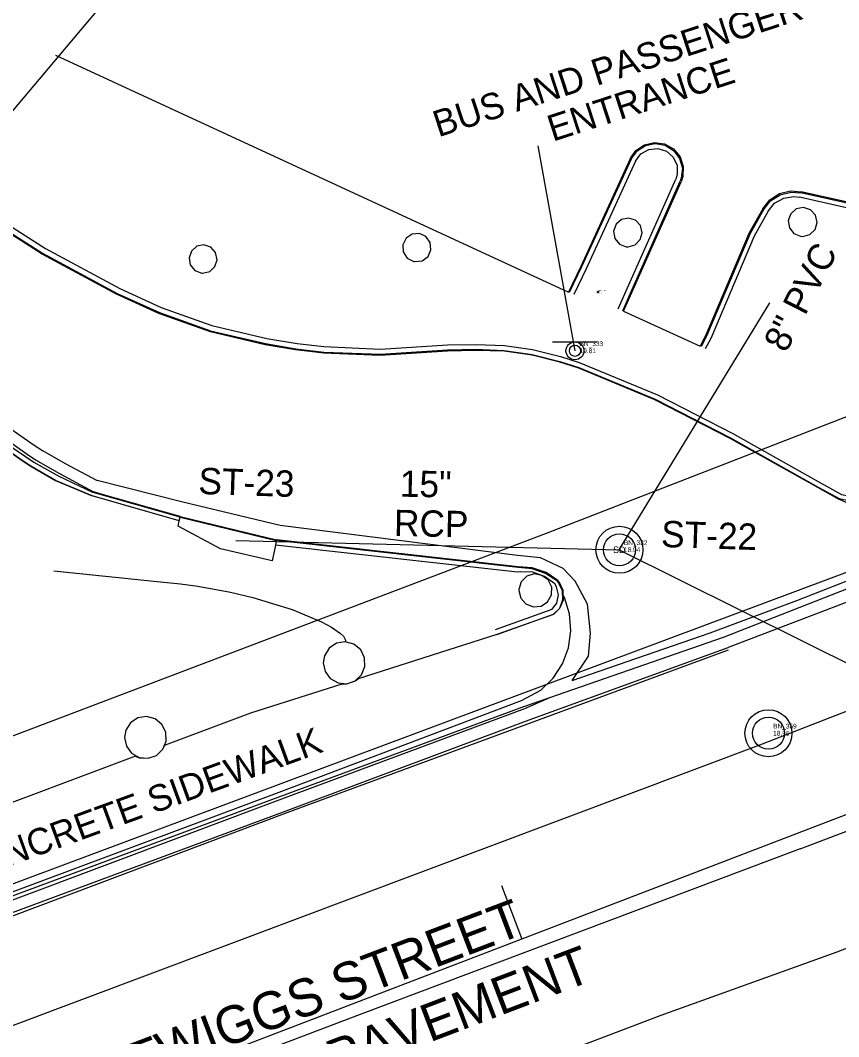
# Model space of a CAD drawing. Extents: x 509744 to 512285, y 1314862 to 1316822.
# Drawn here: x 510729.8 to 510816.7, y 1315517.7 to 1315625.7 of the extents above; entities that cross this region are included whole.
import ezdxf

# ---------------------------------------------------------------- set-up
doc = ezdxf.new("R2010")
doc.units = 0
for name, color, linetype in [('BaselineSurvey', 7, 'Continuous'), ('CGBack_ep', 7, 'Continuous'), ('CGep_ep', 7, 'Continuous'), ('CGFace_ep', 7, 'Continuous'), ('Driveway_ep', 7, 'Continuous'), ('ElecAer_ep', 7, 'Continuous'), ('GroundShot_ep', 7, 'Continuous'), ('InletCurb_ep', 7, 'Continuous'), ('LaneLine_ep', 7, 'Continuous'), ('LARWLine_ep', 7, 'Continuous'), ('ManholeSW_ep', 7, 'Continuous'), ('ManholeUnknown_ep', 7, 'Continuous'), ('NonPlottingEle_dp', 7, 'Continuous'), ('PavtAsphalt_ep', 7, 'Continuous'), ('PavtAsphaltCrown_ep', 7, 'Continuous'), ('PilingColumn_ep', 7, 'Continuous'), ('PipeCulvert_ep', 7, 'Continuous'), ('PMRK_ep', 7, 'Continuous'), ('SidewalkBack_ep', 7, 'Continuous'), ('SignSingle_ep', 7, 'Continuous'), ('TextElevLabel', 7, 'Continuous'), ('TextPtLabel', 7, 'Continuous'), ('TextTopoLabel_ep', 7, 'Continuous')]:
    doc.layers.add(name, color=color, linetype=linetype)

msp = doc.modelspace()

# ---------------------------------------------------------------- linework, layer by layer
at = {"layer": 'BaselineSurvey'}
for p, q in [((509756.06, 1315134.11), (510956.77, 1315594.74)), ((510783.08, 1315528.11), (510780.93, 1315533.71))]:
    msp.add_line(p, q, dxfattribs=at)
at = {"layer": 'CGBack_ep'}
for p, q in [((510746.65, 1315572.52), (510737.41, 1315575.2)), ((510782.61, 1315567.08), (510756.88, 1315569.96)), ((510786.26, 1315563.09), (510780.23, 1315560.95))]:
    msp.add_line(p, q, dxfattribs=at)
for points in [[(510737.41, 1315575.2), (510733.49, 1315576.82), (510730.86, 1315578.34), (510729.97, 1315578.94), (510727.51, 1315580.64), (510725.08, 1315582.41), (510722.77, 1315584.35), (510721.08, 1315585.67), (510709.18, 1315595.32), (510686.17, 1315614.58), (510666.79, 1315630.63)], [(510666.79, 1315630.63), (510686.17, 1315614.58), (510709.18, 1315595.32), (510721.08, 1315585.67), (510722.77, 1315584.35), (510725.08, 1315582.41), (510727.51, 1315580.64), (510729.97, 1315578.94), (510730.86, 1315578.34), (510733.49, 1315576.82), (510737.41, 1315575.2)], [(510795.16, 1315610.77), (510795.73, 1315611.55), (510796.56, 1315612.02), (510797.52, 1315612.13), (510798.44, 1315611.83), (510799.16, 1315611.2), (510799.57, 1315610.32), (510799.59, 1315609.36), (510799.43, 1315608.85)], [(510795.16, 1315610.77), (510789.9, 1315599.32), (510788.59, 1315596.59)], [(510793.32, 1315595.08), (510794.03, 1315596.65), (510799.43, 1315608.85)], [(510809.24, 1315605.45), (510809.94, 1315606.3), (510810.9, 1315606.84), (510811.98, 1315607.01), (510812.57, 1315606.94)], [(510817.57, 1315605.8), (510812.57, 1315606.94)], [(510725.8, 1315605.69), (510732.42, 1315601.49), (510740.33, 1315597.22), (510744.74, 1315595.23), (510750.12, 1315593.3), (510755.96, 1315591.92), (510759.18, 1315591.39), (510762.03, 1315591.05), (510768.03, 1315590.78), (510775.17, 1315591.25), (510778.23, 1315591.29), (510781.23, 1315591.16), (510784.21, 1315590.76), (510787.16, 1315590.01), (510789.17, 1315589.37), (510797.48, 1315585.93), (510805.5, 1315581.83), (510814.81, 1315576.58), (510817.04, 1315575.34), (510819.79, 1315574.76), (510822.54, 1315575.56), (510828.16, 1315577.64), (510830.98, 1315578.69), (510831.57, 1315578.9)], [(510809.24, 1315605.45), (510807.77, 1315602.81), (510803.14, 1315591.91), (510802.57, 1315590.81)], [(510786.56, 1315565.83), (510785.49, 1315566.62), (510784.24, 1315567.06), (510782.92, 1315567.12), (510782.61, 1315567.08)], [(510786.26, 1315563.09), (510786.8, 1315563.79), (510786.97, 1315564.66), (510786.75, 1315565.52), (510786.56, 1315565.83)], [(510785.1, 1315554.51), (510786.4, 1315555.79), (510787.39, 1315557.32), (510788.03, 1315559.02), (510788.28, 1315560.83), (510788.13, 1315562.64), (510787.59, 1315564.38), (510787.53, 1315564.51)], [(510717.8, 1315528.92), (510757.28, 1315543.68), (510783.02, 1315553.43), (510785.1, 1315554.51)]]:
    msp.add_lwpolyline(points, dxfattribs=at)
at = {"layer": 'CGep_ep'}
for p, q in [((510782.68, 1315567.64), (510756.99, 1315570.52)), ((510786.42, 1315562.57), (510780.41, 1315560.46)), ((510786.06, 1315553.74), (510804.49, 1315560.17))]:
    msp.add_line(p, q, dxfattribs=at)
for points in [[(510667.94, 1315630.71), (510686.68, 1315615.13), (510709.65, 1315595.9), (510721.53, 1315586.23), (510723.21, 1315584.89), (510725.56, 1315583.06), (510728.03, 1315581.34), (510730.49, 1315579.63), (510731.38, 1315579.03), (510733.92, 1315577.57), (510737.54, 1315575.61)], [(510746.75, 1315573), (510738.35, 1315575.38), (510737.54, 1315575.61)], [(510746.75, 1315573), (510754.93, 1315571), (510756.99, 1315570.52)], [(510804.49, 1315560.17), (510821.42, 1315566.79), (510835.46, 1315572.07)], [(510786.91, 1315566.17), (510785.64, 1315567.02), (510784.18, 1315567.52), (510782.68, 1315567.64)], [(510786.42, 1315562.57), (510787.12, 1315563.25), (510787.49, 1315564.14), (510787.47, 1315565.11), (510787.06, 1315565.98), (510786.91, 1315566.17)], [(510719.67, 1315528.77), (510757.54, 1315542.97), (510783.38, 1315552.57), (510786.06, 1315553.74)]]:
    msp.add_lwpolyline(points, dxfattribs=at)
at = {"layer": 'CGFace_ep'}
for points in [[(510667.61, 1315630.66), (510686.5, 1315614.93), (510709.48, 1315595.7), (510721.36, 1315586.02), (510723.05, 1315584.7), (510725.37, 1315582.8), (510727.83, 1315581.08), (510730.3, 1315579.37), (510731.19, 1315578.78), (510733.78, 1315577.31), (510737.52, 1315575.56)], [(510794.69, 1315610.99), (510795.31, 1315611.86), (510796.2, 1315612.44), (510797.24, 1315612.65), (510798.29, 1315612.47), (510799.2, 1315611.91), (510799.84, 1315611.06), (510800.13, 1315610.04), (510800.02, 1315608.98), (510799.9, 1315608.64)], [(510794.69, 1315610.99), (510789.42, 1315599.55), (510788.1, 1315596.82)], [(510793.79, 1315594.86), (510794.46, 1315596.41), (510799.9, 1315608.64)], [(510808.74, 1315605.61), (510809.49, 1315606.55), (510810.51, 1315607.19), (510811.68, 1315607.47), (510812.69, 1315607.39)], [(510817.66, 1315606.31), (510812.69, 1315607.39)], [(510808.74, 1315605.61), (510807.33, 1315603.08), (510802.69, 1315592.15), (510802.12, 1315591.05)], [(510725.41, 1315605.24), (510732.13, 1315600.99), (510740.05, 1315596.72), (510744.54, 1315594.69), (510749.99, 1315592.74), (510755.83, 1315591.37), (510759.04, 1315590.83), (510762.03, 1315590.47), (510768.03, 1315590.24), (510775.17, 1315590.71), (510778.19, 1315590.78), (510781.19, 1315590.64), (510784.16, 1315590.23), (510787.11, 1315589.48), (510789.12, 1315588.84), (510797.24, 1315585.46), (510805.25, 1315581.36), (510814.55, 1315576.12), (510816.8, 1315574.92), (510819.69, 1315574.29), (510822.69, 1315575.14), (510828.31, 1315577.22), (510831.13, 1315578.27), (510831.72, 1315578.48)], [(510746.74, 1315572.92), (510737.52, 1315575.56)], [(510717.96, 1315528.51), (510729.22, 1315532.75), (510757.44, 1315543.24), (510783.29, 1315552.78), (510786.06, 1315553.74)]]:
    msp.add_lwpolyline(points, dxfattribs=at)
at = {"layer": 'Driveway_ep'}
for p, q in [((510733.5, 1315622.05), (510788.04, 1315596.86)), ((510793.89, 1315594.81), (510800, 1315608.59)), ((510793.89, 1315594.81), (510802.01, 1315591.1))]:
    msp.add_line(p, q, dxfattribs=at)
for points in [[(510668.18, 1315632.26), (510687.57, 1315616.1), (510710.48, 1315596.92), (510722.36, 1315587.25), (510724.06, 1315585.94), (510726.31, 1315584.05), (510728.75, 1315582.3), (510731.22, 1315580.59), (510732.11, 1315580), (510734.53, 1315578.61), (510737.93, 1315576.83)], [(510794.58, 1315611.03), (510795.2, 1315611.92), (510796.1, 1315612.52), (510797.16, 1315612.77), (510798.24, 1315612.61), (510799.18, 1315612.08), (510799.88, 1315611.24), (510800.23, 1315610.22), (510800.18, 1315609.13), (510800, 1315608.59)], [(510794.58, 1315611.03), (510789.35, 1315599.58), (510788.04, 1315596.86)], [(510862.42, 1315590.32), (510862.8, 1315591.06), (510863.34, 1315592.39), (510863.64, 1315594.19), (510863.51, 1315595.69), (510862.64, 1315598.57), (510862.4, 1315599.05), (510860.68, 1315601.51), (510858.97, 1315603.41), (510856.66, 1315605.36), (510854.02, 1315606.78), (510851.89, 1315607.7), (510848.99, 1315608.42), (510846.01, 1315608.77), (510845.34, 1315608.77), (510839.35, 1315608.16), (510836.4, 1315607.62), (510832.77, 1315606.91), (510827.02, 1315606.06), (510824.02, 1315605.91), (510821.02, 1315606.02), (510820.64, 1315606.01), (510817.68, 1315606.41), (510812.74, 1315607.53)], [(510808.67, 1315605.71), (510809.42, 1315606.66), (510810.44, 1315607.32), (510811.62, 1315607.61), (510812.74, 1315607.53)], [(510808.67, 1315605.71), (510807.23, 1315603.14), (510802.58, 1315592.2), (510802.01, 1315591.1)], [(510832.44, 1315571.96), (510829.41, 1315571.84), (510825.35, 1315571.97), (510821.57, 1315572.75), (510816.74, 1315574.82), (510814.52, 1315576.06), (510805.22, 1315581.3), (510797.21, 1315585.4), (510789.12, 1315588.78), (510787.11, 1315589.41), (510784.16, 1315590.16), (510781.18, 1315590.57), (510778.18, 1315590.64), (510775.16, 1315590.57), (510768.02, 1315590.1), (510762.03, 1315590.35), (510759.02, 1315590.71), (510755.8, 1315591.25), (510749.96, 1315592.63), (510744.5, 1315594.58), (510739.99, 1315596.62), (510732.07, 1315600.88), (510725.35, 1315605.16)], [(510788.43, 1315555.54), (510790.17, 1315558.13), (510790.37, 1315560.6), (510790.06, 1315563.68), (510788.75, 1315566.1), (510787.45, 1315567.47), (510785.04, 1315568.58), (510782.62, 1315568.85), (510757.37, 1315572.02), (510747.05, 1315574.52), (510737.93, 1315576.83)], [(510788.43, 1315555.54), (510803.09, 1315560.61), (510812.3, 1315564.06), (510832.44, 1315571.96)]]:
    msp.add_lwpolyline(points, dxfattribs=at)
at = {"layer": 'ElecAer_ep'}
msp.add_lwpolyline([(510673.59, 1315425.92), (510652.87, 1315530.2), (510676.08, 1315553.36), (510865.37, 1315778.14)], dxfattribs=at)
at = {"layer": 'GroundShot_ep'}
for p, q in [((510791.17, 1315596.73), (510791.17, 1315596.98)), ((510791.29, 1315596.86), (510791.04, 1315596.86))]:
    msp.add_line(p, q, dxfattribs=at)
at = {"layer": 'InletCurb_ep'}
msp.add_lwpolyline([(510756.97, 1315570.44), (510756.88, 1315569.96), (510756.53, 1315568.27), (510751.04, 1315569.55), (510746.54, 1315571.97), (510746.65, 1315572.52), (510746.74, 1315572.92)], close=True, dxfattribs=at)
at = {"layer": 'LaneLine_ep'}
for points in [[(511061.54, 1315628.93), (511044.44, 1315627.39), (511035.76, 1315626.13), (511004.66, 1315620.37), (510995.94, 1315617.75), (510966.1, 1315607.9), (510957.71, 1315604.65), (510928.62, 1315594.05), (510919.98, 1315590.9), (510890.84, 1315579.91), (510852.48, 1315565.44), (510817.09, 1315552.08), (510808.62, 1315548.79)], [(510816.6, 1315526.69), (510837.31, 1315534.81), (510873.94, 1315548.81), (510895.29, 1315556.58), (510940.23, 1315574.31), (510982.42, 1315590.03), (510986.67, 1315591.45), (511017.56, 1315600.61), (511033.42, 1315603.87), (511064.33, 1315607.05)], [(510640.96, 1315460.4), (510676.28, 1315473.76), (510723.03, 1315491.51), (510797.88, 1315519.97), (510816.6, 1315526.69)]]:
    msp.add_lwpolyline(points, dxfattribs=at)
at = {"layer": 'LARWLine_ep'}
for p, q in [((510994.57, 1315652.44), (510785.64, 1315571.2)), ((510785.64, 1315571.2), (510586.6, 1315495.53))]:
    msp.add_line(p, q, dxfattribs=at)
at = {"layer": 'ManholeSW_ep'}
for radius in [2.5, 1.7]:
    msp.add_circle((510793.44, 1315569.45), radius, dxfattribs=at)
at = {"layer": 'ManholeUnknown_ep'}
for radius in [2.5, 1.7]:
    msp.add_circle((510809.28, 1315549.95), radius, dxfattribs=at)
at = {"layer": 'PavtAsphalt_ep'}
for points in [[(510836.08, 1315570.49), (510821.91, 1315565.53), (510805, 1315559.08)], [(510758, 1315541.71), (510783.83, 1315551.37), (510805, 1315559.08), (510805, 1315559.08)], [(510589.41, 1315479.17), (510591.74, 1315480.02), (510664.28, 1315506.82), (510711.13, 1315524.28), (510758, 1315541.71)]]:
    msp.add_lwpolyline(points, dxfattribs=at)
at = {"layer": 'PavtAsphaltCrown_ep'}
for points in [[(510812.66, 1315537.66), (510840.71, 1315548.34), (510875.46, 1315561.64), (510912.48, 1315575.94), (510943.39, 1315587.16), (510967.06, 1315595.76)], [(510812.66, 1315537.66), (510765.87, 1315520.04), (510719.12, 1315502.28), (510621.06, 1315465.12)]]:
    msp.add_lwpolyline(points, dxfattribs=at)
at = {"layer": 'PilingColumn_ep'}
for points in [[(510812.93, 1315602.77), (510813.68, 1315602.98), (510814.23, 1315603.52), (510814.45, 1315604.27), (510814.27, 1315605.03), (510813.74, 1315605.6), (510813, 1315605.85), (510812.24, 1315605.7), (510811.65, 1315605.19), (510811.38, 1315604.47), (510811.5, 1315603.7), (510811.98, 1315603.08), (510812.7, 1315602.79)], [(510794.37, 1315601.67), (510795.12, 1315601.88), (510795.66, 1315602.43), (510795.87, 1315603.17), (510795.69, 1315603.93), (510795.16, 1315604.49), (510794.42, 1315604.73), (510793.66, 1315604.57), (510793.08, 1315604.06), (510792.82, 1315603.32), (510792.95, 1315602.56), (510793.44, 1315601.96), (510794.17, 1315601.68)], [(510771.71, 1315600.09), (510772.48, 1315600.19), (510773.1, 1315600.65), (510773.4, 1315601.36), (510773.32, 1315602.13), (510772.87, 1315602.75), (510772.18, 1315603.08), (510771.41, 1315603.02), (510770.77, 1315602.58), (510770.43, 1315601.89), (510770.47, 1315601.12), (510770.89, 1315600.47), (510771.57, 1315600.12)], [(510749.14, 1315598.87), (510749.89, 1315599.04), (510750.45, 1315599.56), (510750.68, 1315600.29), (510750.52, 1315601.05), (510750.01, 1315601.62), (510749.28, 1315601.87), (510748.53, 1315601.72), (510747.95, 1315601.22), (510747.7, 1315600.5), (510747.83, 1315599.74), (510748.32, 1315599.15), (510749.04, 1315598.88)], [(510782.76, 1315565.13), (510782.96, 1315564.32), (510783.5, 1315563.69), (510784.28, 1315563.39), (510785.11, 1315563.47), (510785.8, 1315563.93), (510786.21, 1315564.65), (510786.24, 1315565.49), (510785.88, 1315566.24), (510785.19, 1315566.71), (510784.39, 1315566.88), (510783.6, 1315566.63), (510783.01, 1315566.04), (510782.76, 1315565.24)], [(510761.96, 1315557.43), (510762.15, 1315556.51), (510762.71, 1315555.75), (510763.53, 1315555.29), (510764.47, 1315555.21), (510765.36, 1315555.52), (510766.04, 1315556.17), (510766.39, 1315557.04), (510766.36, 1315557.98), (510765.94, 1315558.82), (510765.21, 1315559.42), (510764.3, 1315559.66), (510763.37, 1315559.51), (510762.59, 1315558.99), (510762.09, 1315558.19)], [(510740.83, 1315549.5), (510741.03, 1315548.58), (510741.59, 1315547.82), (510742.41, 1315547.36), (510743.34, 1315547.28), (510744.23, 1315547.59), (510744.91, 1315548.24), (510745.26, 1315549.11), (510745.23, 1315550.05), (510744.81, 1315550.89), (510744.08, 1315551.49), (510743.18, 1315551.73), (510742.25, 1315551.58), (510741.46, 1315551.06), (510740.96, 1315550.26)]]:
    msp.add_lwpolyline(points, close=True, dxfattribs=at)
at = {"layer": 'PipeCulvert_ep'}
for p, q in [((510712.14, 1315527.66), (510960.6, 1315620.54)), ((510793.42, 1315569.46), (510809.41, 1315595.7)), ((510752.68, 1315570.44), (510793.42, 1315569.46)), ((510793.42, 1315569.46), (510831, 1315550.75))]:
    msp.add_line(p, q, dxfattribs=at)
at = {"layer": 'PMRK_ep'}
for points in [[(510805, 1315558.78), (510758.08, 1315541.48), (510711.29, 1315523.86), (510610.99, 1315486.48)], [(510808.62, 1315548.79), (510715, 1315513.64), (510693.3, 1315505.37)]]:
    msp.add_lwpolyline(points, dxfattribs=at)
at = {"layer": 'SidewalkBack_ep'}
for p, q in [((510782.67, 1315567.56), (510756.97, 1315570.44)), ((510780.41, 1315560.46), (510786.42, 1315562.59)), ((510780.41, 1315560.46), (510765.68, 1315555.73)), ((510763.95, 1315555.18), (510754.23, 1315552.09))]:
    msp.add_line(p, q, dxfattribs=at)
for points in [[(510786.85, 1315566.11), (510785.6, 1315566.94), (510784.18, 1315567.44), (510782.68, 1315567.56), (510782.67, 1315567.56)], [(510786.42, 1315562.59), (510787.09, 1315563.26), (510787.44, 1315564.15), (510787.4, 1315565.1), (510786.98, 1315565.96), (510786.85, 1315566.11)], [(510763.95, 1315555.18), (510764.47, 1315555.2), (510765.36, 1315555.52), (510765.68, 1315555.73), (510765.68, 1315555.73)], [(510754.23, 1315552.09), (510745.15, 1315548.69)], [(510742.02, 1315547.52), (510742.39, 1315547.32), (510743.34, 1315547.28), (510744.24, 1315547.57), (510744.91, 1315548.24), (510745.07, 1315548.59), (510745.15, 1315548.69)], [(510742.02, 1315547.52), (510723.85, 1315540.72)]]:
    msp.add_lwpolyline(points, dxfattribs=at)
at = {"layer": 'SignSingle_ep'}
msp.add_line((510786.34, 1315591.56), (510791.09, 1315591.56), dxfattribs=at)
for radius in [0.95, 0.594]:
    msp.add_circle((510788.71, 1315590.61), radius, dxfattribs=at)
at = {"layer": 'TextTopoLabel_ep'}
msp.add_line((510784.76, 1315612.39), (510788.71, 1315590.61), dxfattribs=at)
msp.add_lwpolyline([(510733.33, 1315567.22), (510743.95, 1315566.13), (510746.8, 1315565.84), (510748.63, 1315565.58), (510752.09, 1315564.94), (510754.49, 1315564.38), (510758.64, 1315563.11), (510761.79, 1315561.79), (510762.82, 1315561.24), (510763.79, 1315560.56), (510764.1, 1315560.25), (510764.31, 1315559.85), (510764.3, 1315559.68)], dxfattribs=at)

# ---------------------------------------------------------------- texts
at = {"layer": 'ManholeSW_ep'}
msp.add_text('SD', height=0.7, dxfattribs=at).set_placement((510792.77, 1315569.1))
at = {"layer": 'NonPlottingEle_dp'}
for s, rotation, p in [('8" PVC', 62.9032, (510811.15, 1315590.3)), ('ST-23', 358.1578, (510748.66, 1315575.39)), ('15"', 358.9851, (510770.08, 1315575.1)), (' RCP', 358.9851, (510768.42, 1315570.93)), ('ST-22', 358.1578, (510797.84, 1315569.75))]:
    msp.add_text(s, height=2.8, rotation=rotation, dxfattribs=at).set_placement(p)
at = {"layer": 'TextElevLabel'}
for s, height, p in [('20.06', 0.1, (510791.27, 1315596.81)), ('19.81', 0.5, (510789.21, 1315590.36)), ('18.94', 0.5, (510793.92, 1315569.21)), ('18.96', 0.5, (510809.78, 1315549.7))]:
    msp.add_text(s, height=height, dxfattribs=at).set_placement(p)
at = {"layer": 'TextPtLabel'}
for s, height, p in [('DEFAULT_51', 0.1, (510791.27, 1315596.96)), ('BN_333', 0.5, (510789.21, 1315591.11)), ('BN_332', 0.5, (510793.92, 1315569.96)), ('BN_359', 0.5, (510809.78, 1315550.45))]:
    msp.add_text(s, height=height, dxfattribs=at).set_placement(p)
at = {"layer": 'TextTopoLabel_ep'}
for s, height, rotation, p in [('BUS AND PASSENGER', 2.8, 17.9869, (510774.19, 1315613.3)), ('ENTRANCE', 2.8, 17.9869, (510786.35, 1315612.83)), ('CONCRETE SIDEWALK', 2.8, 20.0424, (510723.2, 1315533.82)), ('TWIGGS STREET', 4, 20.8127, (510742.12, 1315512.92)), ('ASPHALT PAVEMENT', 4, 20.8127, (510739.09, 1315504.06))]:
    msp.add_text(s, height=height, rotation=rotation, dxfattribs=at).set_placement(p)

doc.saveas('drawing.dxf')
